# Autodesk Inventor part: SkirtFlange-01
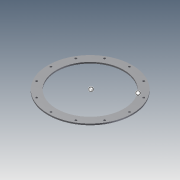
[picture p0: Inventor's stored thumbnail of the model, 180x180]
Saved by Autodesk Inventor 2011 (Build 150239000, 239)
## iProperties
Created: 2010-06
Part Number: SkirtFlange-01
Document SubType Name: Modeling
Designer: mklassen
Density: 1 g/cm^3
OD: 24.000 in
THK: 0.500 in
WDT: 3.000 in
BHN: 12.000 ul
BHD: 0.750 in
BCD: 14.000 in
Author: mklassen
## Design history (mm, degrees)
sketch "skSkirtFlange"
  geometry: C1 r 304.8 at (0, 0); C2 r 381 at (0, 0); 1 further point
  constraints: 2 centre point, 2 coincident
  dimensions: "d0" = 76.2 radial gap between concentric circles of C2 C1 (derived); "d1" = 609.6 diameter of C1 (derived)
extrude "SkirtFlange" new body sketch "skSkirtFlange" stored distance "d2" = 12.7 (derived); taper "d3" = 0 deg
sketch "skBoltHole"
  geometry: C1 r 304.8 at (0, 0) reference; 2 further points
  constraints: 1 coincident, 1 vertical alignment
  dimensions: "d7" = 355.6 distance of point (0, 355.6) point (0, 0) (= BCD)
hole "BoltHole" sketch "skBoltHole" at (0, 355.6) diameter "d8" = 19.05 (derived); stored, may be unused: countersink angle "d12" = 82 deg, drill point angle "d14" = 118 deg; dims "d9" = 19.05, "d10" = 9.525, "d11" = 6.35, "d13" = 25.4
pattern_circular "BoltCircle" dims angle "d16" = 360 deg
body "Solid1"
other parameters: "BCD" = 355.6 [user parameter; used in 2 equation terms], "d4" = 0, "d5" = 0, "d6" = 0
